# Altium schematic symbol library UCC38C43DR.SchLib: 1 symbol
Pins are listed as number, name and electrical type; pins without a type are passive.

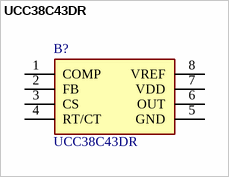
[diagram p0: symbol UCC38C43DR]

## UCC38C43DR
designator B?
Texas Instruments UCC38C43DR, PWM Current Mode Controller, 0.2 A, 1000 kHz 8-Pin SOIC; Geometry.Height: 1.75mm
footprint SOIC127P600X175-8N
pins: 1 COMP, 2 FB, 3 CS, 4 RT/CT, 5 GND, 6 OUT, 7 VDD, 8 VREF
